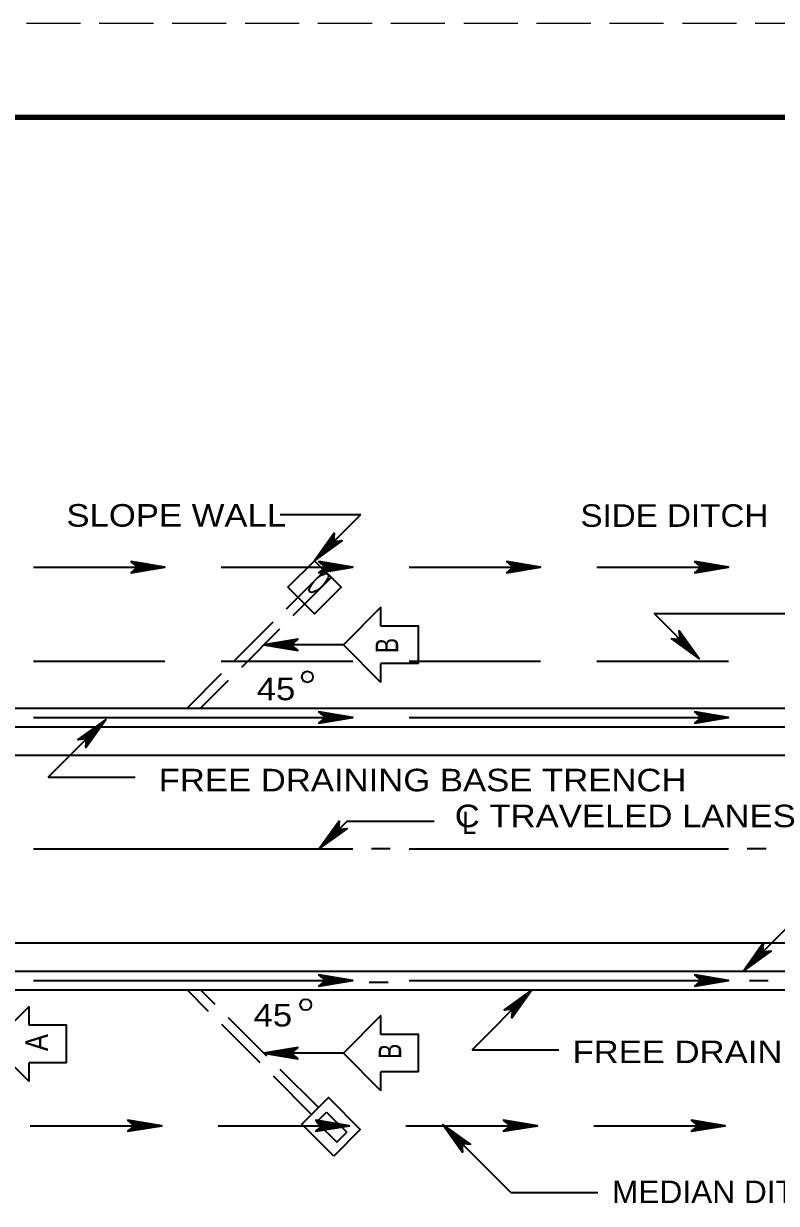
# Model space of a CAD drawing. Extents: x -48732 to -48696.6, y -117659.8 to -117637.8.
# Drawn here: x -48725.39 to -48721.38, y -117644.13 to -117637.85 of the extents above; entities that cross this region are included whole.
import ezdxf

# ---------------------------------------------------------------- set-up
doc = ezdxf.new("R2010")
doc.units = 0
doc.header["$LTSCALE"] = 0.048
doc.linetypes.add('LONG_DASHED', pattern=[7.5, 6, -1.5])
doc.layers.add('1', color=7, linetype='Continuous', lineweight=25)
doc.layers.add('3', color=7, linetype='Continuous', lineweight=35)

msp = doc.modelspace()

# ---------------------------------------------------------------- linework, layer by layer
at = {"layer": '1', "linetype": 'LONG_DASHED'}
msp.add_line((-48696.76492, -117637.84817), (-48731.96492, -117637.84817), dxfattribs=at)
at = {"layer": '1', "lineweight": 158}
msp.add_line((-48696.84825, -117638.34817), (-48729.34825, -117638.34817), dxfattribs=at)
at = {"layer": '3'}
for p, q in [((-48724.02558, -117640.46117), (-48723.59658, -117640.46117)), ((-48723.84358, -117640.70817), (-48723.59658, -117640.46117)), ((-48725.33958, -117640.74217), (-48724.63958, -117640.74217)), ((-48724.33958, -117640.74217), (-48723.63958, -117640.74217)), ((-48723.33958, -117640.74217), (-48722.63958, -117640.74217)), ((-48722.33958, -117640.74217), (-48721.63958, -117640.74217)), ((-48723.48958, -117640.95517), (-48723.68958, -117641.15517)), ((-48723.48958, -117641.05517), (-48723.48958, -117640.95517)), ((-48722.03458, -117640.98917), (-48721.33458, -117640.98917)), ((-48721.79558, -117641.22917), (-48722.03458, -117640.98917)), ((-48723.68958, -117641.15517), (-48724.11258, -117641.15517)), ((-48723.48958, -117641.35517), (-48723.68958, -117641.15517)), ((-48725.33958, -117641.24217), (-48724.63958, -117641.24217)), ((-48724.33958, -117641.24217), (-48723.63958, -117641.24217)), ((-48723.28958, -117641.25517), (-48723.48958, -117641.25517)), ((-48723.48958, -117641.35517), (-48723.48958, -117641.25517)), ((-48723.33958, -117641.24217), (-48722.63958, -117641.24217)), ((-48722.33958, -117641.24217), (-48721.63958, -117641.24217)), ((-48727.33958, -117641.49217), (-48718.76717, -117641.49217)), ((-48727.33958, -117641.59217), (-48718.76717, -117641.59217)), ((-48725.33958, -117641.54217), (-48723.63958, -117641.54217)), ((-48725.26158, -117641.86017), (-48724.95458, -117641.55317)), ((-48723.33958, -117641.54217), (-48721.63958, -117641.54217)), ((-48721.5605, -117642.89217), (-48720.2605, -117641.59217)), ((-48727.33958, -117641.74217), (-48717.32258, -117641.74217)), ((-48725.26158, -117641.86017), (-48724.79858, -117641.86017)), ((-48725.33958, -117642.24217), (-48723.63958, -117642.24217)), ((-48723.43958, -117642.24217), (-48723.53958, -117642.24217)), ((-48723.33958, -117642.24217), (-48721.63958, -117642.24217)), ((-48721.43958, -117642.24217), (-48721.53958, -117642.24217)), ((-48727.33958, -117642.74217), (-48717.32258, -117642.74217)), ((-48727.43958, -117642.89217), (-48718.76717, -117642.89217)), ((-48725.33958, -117642.94217), (-48723.63958, -117642.94217)), ((-48723.45158, -117642.95217), (-48723.55158, -117642.95217)), ((-48723.33958, -117642.94217), (-48721.63958, -117642.94217)), ((-48721.42758, -117642.94417), (-48721.52758, -117642.94417)), ((-48727.43958, -117642.99217), (-48718.76717, -117642.99217)), ((-48723.00475, -117643.311), (-48722.68592, -117642.99217)), ((-48725.36258, -117643.08017), (-48725.56258, -117643.28017)), ((-48725.36258, -117643.18017), (-48725.36258, -117643.08017)), ((-48723.48958, -117643.12917), (-48723.68958, -117643.32917)), ((-48723.48958, -117643.22917), (-48723.48958, -117643.12917)), ((-48725.36258, -117643.48017), (-48725.56258, -117643.28017)), ((-48723.68958, -117643.32917), (-48724.11258, -117643.32917)), ((-48723.48958, -117643.52917), (-48723.68958, -117643.32917)), ((-48723.00475, -117643.311), (-48722.54175, -117643.311)), ((-48725.16258, -117643.38017), (-48725.36258, -117643.38017)), ((-48725.36258, -117643.48017), (-48725.36258, -117643.38017)), ((-48723.28958, -117643.42917), (-48723.48958, -117643.42917)), ((-48723.48958, -117643.52917), (-48723.48958, -117643.42917)), ((-48723.83258, -117643.69617), (-48723.77958, -117643.64317)), ((-48723.77958, -117643.64317), (-48723.67158, -117643.75017)), ((-48725.35658, -117643.71517), (-48724.65658, -117643.71517)), ((-48724.35658, -117643.71517), (-48723.65658, -117643.71517)), ((-48723.83258, -117643.69617), (-48723.72458, -117643.80317)), ((-48723.35658, -117643.71517), (-48722.65658, -117643.71517)), ((-48722.79758, -117644.07117), (-48723.16058, -117643.70817)), ((-48722.35658, -117643.71517), (-48721.65658, -117643.71517)), ((-48723.72458, -117643.80317), (-48723.67158, -117643.75017)), ((-48722.79758, -117644.07117), (-48722.33458, -117644.07117))]:
    msp.add_line(p, q, dxfattribs=at)
at = {"layer": '3', "linetype": 'LONG_DASHED'}
for p, q in [((-48723.79058, -117640.76117), (-48724.52158, -117641.49217)), ((-48723.75458, -117640.79717), (-48724.44958, -117641.49217)), ((-48723.85858, -117643.65517), (-48724.52158, -117642.99217)), ((-48723.82258, -117643.61917), (-48724.44958, -117642.99217))]:
    msp.add_line(p, q, dxfattribs=at)
at = {"layer": '3'}
for points in [[(-48723.73758, -117640.56017), (-48723.84358, -117640.70817), (-48723.69558, -117640.60217), (-48723.70058, -117640.60217), (-48723.83058, -117640.69517), (-48723.73758, -117640.56517), (-48723.73858, -117640.57117), (-48723.81758, -117640.68217), (-48723.70658, -117640.60317), (-48723.71258, -117640.60417), (-48723.80458, -117640.66917), (-48723.73958, -117640.57717), (-48723.73958, -117640.58317), (-48723.79158, -117640.65617), (-48723.71858, -117640.60417), (-48723.72458, -117640.60517), (-48723.77958, -117640.64417), (-48723.74058, -117640.58917), (-48723.74058, -117640.59517), (-48723.76658, -117640.63117), (-48723.73058, -117640.60517), (-48723.73658, -117640.60617), (-48723.75358, -117640.61817), (-48723.74158, -117640.60117), (-48723.73758, -117640.56017), (-48723.74158, -117640.60617), (-48723.69558, -117640.60217)], [(-48724.81958, -117640.77217), (-48724.63958, -117640.74217), (-48724.81958, -117640.71217), (-48724.81458, -117640.71617), (-48724.65758, -117640.74217), (-48724.81558, -117640.76817), (-48724.81058, -117640.76417), (-48724.67658, -117640.74217), (-48724.81058, -117640.72017), (-48724.80558, -117640.72317), (-48724.69458, -117640.74217), (-48724.80558, -117640.76117), (-48724.80158, -117640.75717), (-48724.71258, -117640.74217), (-48724.80158, -117640.72717), (-48724.79658, -117640.73117), (-48724.73058, -117640.74217), (-48724.79658, -117640.75317), (-48724.79258, -117640.74917), (-48724.74958, -117640.74217), (-48724.79258, -117640.73517), (-48724.78758, -117640.73917), (-48724.76758, -117640.74217), (-48724.78758, -117640.74517), (-48724.81958, -117640.77217), (-48724.78358, -117640.74217), (-48724.81958, -117640.71217)], [(-48723.81958, -117640.77217), (-48723.63958, -117640.74217), (-48723.81958, -117640.71217), (-48723.81458, -117640.71617), (-48723.65758, -117640.74217), (-48723.81558, -117640.76817), (-48723.81058, -117640.76417), (-48723.67658, -117640.74217), (-48723.81058, -117640.72017), (-48723.80558, -117640.72317), (-48723.69458, -117640.74217), (-48723.80558, -117640.76117), (-48723.80158, -117640.75717), (-48723.71258, -117640.74217), (-48723.80158, -117640.72717), (-48723.79658, -117640.73117), (-48723.73058, -117640.74217), (-48723.79658, -117640.75317), (-48723.79258, -117640.74917), (-48723.74958, -117640.74217), (-48723.79258, -117640.73517), (-48723.78758, -117640.73917), (-48723.76758, -117640.74217), (-48723.78758, -117640.74517), (-48723.81958, -117640.77217), (-48723.78358, -117640.74217), (-48723.81958, -117640.71217)], [(-48722.81958, -117640.77217), (-48722.63958, -117640.74217), (-48722.81958, -117640.71217), (-48722.81458, -117640.71617), (-48722.65758, -117640.74217), (-48722.81558, -117640.76817), (-48722.81058, -117640.76417), (-48722.67658, -117640.74217), (-48722.81058, -117640.72017), (-48722.80558, -117640.72317), (-48722.69458, -117640.74217), (-48722.80558, -117640.76117), (-48722.80158, -117640.75717), (-48722.71258, -117640.74217), (-48722.80158, -117640.72717), (-48722.79658, -117640.73117), (-48722.73058, -117640.74217), (-48722.79658, -117640.75317), (-48722.79258, -117640.74917), (-48722.74958, -117640.74217), (-48722.79258, -117640.73517), (-48722.78758, -117640.73917), (-48722.76758, -117640.74217), (-48722.78758, -117640.74517), (-48722.81958, -117640.77217), (-48722.78358, -117640.74217), (-48722.81958, -117640.71217)], [(-48721.81958, -117640.77217), (-48721.63958, -117640.74217), (-48721.81958, -117640.71217), (-48721.81458, -117640.71617), (-48721.65758, -117640.74217), (-48721.81558, -117640.76817), (-48721.81058, -117640.76417), (-48721.67658, -117640.74217), (-48721.81058, -117640.72017), (-48721.80558, -117640.72317), (-48721.69458, -117640.74217), (-48721.80558, -117640.76117), (-48721.80158, -117640.75717), (-48721.71258, -117640.74217), (-48721.80158, -117640.72717), (-48721.79658, -117640.73117), (-48721.73058, -117640.74217), (-48721.79658, -117640.75317), (-48721.79258, -117640.74917), (-48721.74958, -117640.74217), (-48721.79258, -117640.73517), (-48721.78758, -117640.73917), (-48721.76758, -117640.74217), (-48721.78758, -117640.74517), (-48721.81958, -117640.77217), (-48721.78358, -117640.74217), (-48721.81958, -117640.71217)], [(-48723.28958, -117641.25517), (-48723.28958, -117641.05517), (-48723.48958, -117641.05517)], [(-48721.94358, -117641.12317), (-48721.79558, -117641.22917), (-48721.90158, -117641.08117), (-48721.90158, -117641.08617), (-48721.80858, -117641.21617), (-48721.93858, -117641.12317), (-48721.93258, -117641.12417), (-48721.82158, -117641.20317), (-48721.90058, -117641.09217), (-48721.89958, -117641.09817), (-48721.83458, -117641.19017), (-48721.92658, -117641.12517), (-48721.92058, -117641.12517), (-48721.84758, -117641.17717), (-48721.89958, -117641.10417), (-48721.89858, -117641.11017), (-48721.85958, -117641.16517), (-48721.91458, -117641.12617), (-48721.90858, -117641.12617), (-48721.87258, -117641.15217), (-48721.89858, -117641.11617), (-48721.89758, -117641.12217), (-48721.88558, -117641.13917), (-48721.90258, -117641.12717), (-48721.94358, -117641.12317), (-48721.89758, -117641.12717), (-48721.90158, -117641.08117)], [(-48723.93258, -117641.12517), (-48724.11258, -117641.15517), (-48723.93258, -117641.18517), (-48723.93758, -117641.18117), (-48724.09458, -117641.15517), (-48723.93658, -117641.12917), (-48723.94158, -117641.13317), (-48724.07558, -117641.15517), (-48723.94158, -117641.17717), (-48723.94658, -117641.17417), (-48724.05758, -117641.15517), (-48723.94658, -117641.13617), (-48723.95058, -117641.14017), (-48724.03958, -117641.15517), (-48723.95058, -117641.17017), (-48723.95558, -117641.16617), (-48724.02158, -117641.15517), (-48723.95558, -117641.14417), (-48723.95958, -117641.14817), (-48724.00258, -117641.15517), (-48723.95958, -117641.16217), (-48723.96458, -117641.15817), (-48723.98458, -117641.15517), (-48723.96458, -117641.15217), (-48723.93258, -117641.12517), (-48723.96858, -117641.15517), (-48723.93258, -117641.18517)], [(-48723.81958, -117641.57217), (-48723.63958, -117641.54217), (-48723.81958, -117641.51217), (-48723.81458, -117641.51617), (-48723.65758, -117641.54217), (-48723.81558, -117641.56817), (-48723.81058, -117641.56417), (-48723.67658, -117641.54217), (-48723.81058, -117641.52017), (-48723.80558, -117641.52317), (-48723.69458, -117641.54217), (-48723.80558, -117641.56117), (-48723.80158, -117641.55717), (-48723.71258, -117641.54217), (-48723.80158, -117641.52717), (-48723.79658, -117641.53117), (-48723.73058, -117641.54217), (-48723.79658, -117641.55317), (-48723.79258, -117641.54917), (-48723.74958, -117641.54217), (-48723.79258, -117641.53517), (-48723.78758, -117641.53917), (-48723.76758, -117641.54217), (-48723.78758, -117641.54517), (-48723.81958, -117641.57217), (-48723.78358, -117641.54217), (-48723.81958, -117641.51217)], [(-48721.81958, -117641.57217), (-48721.63958, -117641.54217), (-48721.81958, -117641.51217), (-48721.81458, -117641.51617), (-48721.65758, -117641.54217), (-48721.81558, -117641.56817), (-48721.81058, -117641.56417), (-48721.67658, -117641.54217), (-48721.81058, -117641.52017), (-48721.80558, -117641.52317), (-48721.69458, -117641.54217), (-48721.80558, -117641.56117), (-48721.80158, -117641.55717), (-48721.71258, -117641.54217), (-48721.80158, -117641.52717), (-48721.79658, -117641.53117), (-48721.73058, -117641.54217), (-48721.79658, -117641.55317), (-48721.79258, -117641.54917), (-48721.74958, -117641.54217), (-48721.79258, -117641.53517), (-48721.78758, -117641.53917), (-48721.76758, -117641.54217), (-48721.78758, -117641.54517), (-48721.81958, -117641.57217), (-48721.78358, -117641.54217), (-48721.81958, -117641.51217)], [(-48725.06058, -117641.70117), (-48724.95458, -117641.55317), (-48725.10258, -117641.65917), (-48725.09758, -117641.65917), (-48724.96758, -117641.56617), (-48725.06058, -117641.69617), (-48725.05958, -117641.69017), (-48724.98058, -117641.57917), (-48725.09158, -117641.65817), (-48725.08558, -117641.65717), (-48724.99358, -117641.59217), (-48725.05858, -117641.68417), (-48725.05858, -117641.67817), (-48725.00658, -117641.60517), (-48725.07958, -117641.65717), (-48725.07358, -117641.65617), (-48725.01858, -117641.61717), (-48725.05758, -117641.67217), (-48725.05758, -117641.66617), (-48725.03158, -117641.63017), (-48725.06758, -117641.65617), (-48725.06158, -117641.65517), (-48725.04458, -117641.64317), (-48725.05658, -117641.66017), (-48725.06058, -117641.70117), (-48725.05658, -117641.65517), (-48725.10258, -117641.65917)], [(-48723.81758, -117642.24117), (-48723.66958, -117642.09317), (-48723.20658, -117642.09317)], [(-48723.71158, -117642.09317), (-48723.81758, -117642.24117), (-48723.66958, -117642.13517), (-48723.67458, -117642.13517), (-48723.80458, -117642.22817), (-48723.71158, -117642.09817), (-48723.71258, -117642.10417), (-48723.79158, -117642.21517), (-48723.68058, -117642.13617), (-48723.68658, -117642.13717), (-48723.77858, -117642.20217), (-48723.71358, -117642.11017), (-48723.71358, -117642.11617), (-48723.76558, -117642.18917), (-48723.69258, -117642.13717), (-48723.69858, -117642.13817), (-48723.75358, -117642.17717), (-48723.71458, -117642.12217), (-48723.71458, -117642.12817), (-48723.74058, -117642.16417), (-48723.70458, -117642.13817), (-48723.71058, -117642.13917), (-48723.72758, -117642.15117), (-48723.71558, -117642.13417), (-48723.71158, -117642.09317), (-48723.71558, -117642.13917), (-48723.66958, -117642.13517)], [(-48721.4545, -117642.74417), (-48721.5605, -117642.89217), (-48721.4125, -117642.78617), (-48721.4175, -117642.78617), (-48721.5475, -117642.87917), (-48721.4545, -117642.74917), (-48721.4555, -117642.75517), (-48721.5345, -117642.86617), (-48721.4235, -117642.78717), (-48721.4295, -117642.78817), (-48721.5215, -117642.85317), (-48721.4565, -117642.76117), (-48721.4565, -117642.76717), (-48721.5085, -117642.84017), (-48721.4355, -117642.78817), (-48721.4415, -117642.78917), (-48721.4965, -117642.82817), (-48721.4575, -117642.77317), (-48721.4575, -117642.77917), (-48721.4835, -117642.81517), (-48721.4475, -117642.78917), (-48721.4535, -117642.79017), (-48721.4705, -117642.80217), (-48721.4585, -117642.78517), (-48721.4545, -117642.74417), (-48721.4585, -117642.79017), (-48721.4125, -117642.78617)], [(-48723.81958, -117642.97217), (-48723.63958, -117642.94217), (-48723.81958, -117642.91217), (-48723.81458, -117642.91617), (-48723.65758, -117642.94217), (-48723.81558, -117642.96817), (-48723.81058, -117642.96417), (-48723.67658, -117642.94217), (-48723.81058, -117642.92017), (-48723.80558, -117642.92317), (-48723.69458, -117642.94217), (-48723.80558, -117642.96117), (-48723.80158, -117642.95717), (-48723.71258, -117642.94217), (-48723.80158, -117642.92717), (-48723.79658, -117642.93117), (-48723.73058, -117642.94217), (-48723.79658, -117642.95317), (-48723.79258, -117642.94917), (-48723.74958, -117642.94217), (-48723.79258, -117642.93517), (-48723.78758, -117642.93917), (-48723.76758, -117642.94217), (-48723.78758, -117642.94517), (-48723.81958, -117642.97217), (-48723.78358, -117642.94217), (-48723.81958, -117642.91217)], [(-48721.81958, -117642.97217), (-48721.63958, -117642.94217), (-48721.81958, -117642.91217), (-48721.81458, -117642.91617), (-48721.65758, -117642.94217), (-48721.81558, -117642.96817), (-48721.81058, -117642.96417), (-48721.67658, -117642.94217), (-48721.81058, -117642.92017), (-48721.80558, -117642.92317), (-48721.69458, -117642.94217), (-48721.80558, -117642.96117), (-48721.80158, -117642.95717), (-48721.71258, -117642.94217), (-48721.80158, -117642.92717), (-48721.79658, -117642.93117), (-48721.73058, -117642.94217), (-48721.79658, -117642.95317), (-48721.79258, -117642.94917), (-48721.74958, -117642.94217), (-48721.79258, -117642.93517), (-48721.78758, -117642.93917), (-48721.76758, -117642.94217), (-48721.78758, -117642.94517), (-48721.81958, -117642.97217), (-48721.78358, -117642.94217), (-48721.81958, -117642.91217)], [(-48722.79192, -117643.14017), (-48722.68592, -117642.99217), (-48722.83392, -117643.09817), (-48722.82892, -117643.09817), (-48722.69892, -117643.00517), (-48722.79192, -117643.13517), (-48722.79092, -117643.12917), (-48722.71192, -117643.01817), (-48722.82292, -117643.09717), (-48722.81692, -117643.09617), (-48722.72492, -117643.03117), (-48722.78992, -117643.12317), (-48722.78992, -117643.11717), (-48722.73792, -117643.04417), (-48722.81092, -117643.09617), (-48722.80492, -117643.09517), (-48722.74992, -117643.05617), (-48722.78892, -117643.11117), (-48722.78892, -117643.10517), (-48722.76292, -117643.06917), (-48722.79892, -117643.09517), (-48722.79292, -117643.09417), (-48722.77592, -117643.08217), (-48722.78792, -117643.09917), (-48722.79192, -117643.14017), (-48722.78792, -117643.09417), (-48722.83392, -117643.09817)], [(-48725.16258, -117643.38017), (-48725.16258, -117643.18017), (-48725.36258, -117643.18017)], [(-48723.28958, -117643.42917), (-48723.28958, -117643.22917), (-48723.48958, -117643.22917)], [(-48723.93258, -117643.29917), (-48724.11258, -117643.32917), (-48723.93258, -117643.35917), (-48723.93758, -117643.35517), (-48724.09458, -117643.32917), (-48723.93658, -117643.30317), (-48723.94158, -117643.30717), (-48724.07558, -117643.32917), (-48723.94158, -117643.35117), (-48723.94658, -117643.34817), (-48724.05758, -117643.32917), (-48723.94658, -117643.31017), (-48723.95058, -117643.31417), (-48724.03958, -117643.32917), (-48723.95058, -117643.34417), (-48723.95558, -117643.34017), (-48724.02158, -117643.32917), (-48723.95558, -117643.31817), (-48723.95958, -117643.32217), (-48724.00258, -117643.32917), (-48723.95958, -117643.33617), (-48723.96458, -117643.33217), (-48723.98458, -117643.32917), (-48723.96458, -117643.32617), (-48723.93258, -117643.29917), (-48723.96858, -117643.32917), (-48723.93258, -117643.35917)], [(-48724.83658, -117643.74517), (-48724.65658, -117643.71517), (-48724.83658, -117643.68517), (-48724.83158, -117643.68917), (-48724.67458, -117643.71517), (-48724.83258, -117643.74117), (-48724.82758, -117643.73717), (-48724.69358, -117643.71517), (-48724.82758, -117643.69317), (-48724.82258, -117643.69617), (-48724.71158, -117643.71517), (-48724.82258, -117643.73417), (-48724.81858, -117643.73017), (-48724.72958, -117643.71517), (-48724.81858, -117643.70017), (-48724.81358, -117643.70417), (-48724.74758, -117643.71517), (-48724.81358, -117643.72617), (-48724.80958, -117643.72217), (-48724.76658, -117643.71517), (-48724.80958, -117643.70817), (-48724.80458, -117643.71217), (-48724.78458, -117643.71517), (-48724.80458, -117643.71817), (-48724.83658, -117643.74517), (-48724.80058, -117643.71517), (-48724.83658, -117643.68517)], [(-48723.83658, -117643.74517), (-48723.65658, -117643.71517), (-48723.83658, -117643.68517), (-48723.83158, -117643.68917), (-48723.67458, -117643.71517), (-48723.83258, -117643.74117), (-48723.82758, -117643.73717), (-48723.69358, -117643.71517), (-48723.82758, -117643.69317), (-48723.82258, -117643.69617), (-48723.71158, -117643.71517), (-48723.82258, -117643.73417), (-48723.81858, -117643.73017), (-48723.72958, -117643.71517), (-48723.81858, -117643.70017), (-48723.81358, -117643.70417), (-48723.74758, -117643.71517), (-48723.81358, -117643.72617), (-48723.80958, -117643.72217), (-48723.76658, -117643.71517), (-48723.80958, -117643.70817), (-48723.80458, -117643.71217), (-48723.78458, -117643.71517), (-48723.80458, -117643.71817), (-48723.83658, -117643.74517), (-48723.80058, -117643.71517), (-48723.83658, -117643.68517)], [(-48723.01258, -117643.81417), (-48723.16058, -117643.70817), (-48723.05458, -117643.85617), (-48723.05458, -117643.85117), (-48723.14758, -117643.72117), (-48723.01758, -117643.81417), (-48723.02358, -117643.81317), (-48723.13458, -117643.73417), (-48723.05558, -117643.84517), (-48723.05658, -117643.83917), (-48723.12158, -117643.74717), (-48723.02958, -117643.81217), (-48723.03558, -117643.81217), (-48723.10858, -117643.76017), (-48723.05658, -117643.83317), (-48723.05758, -117643.82717), (-48723.09658, -117643.77217), (-48723.04158, -117643.81117), (-48723.04758, -117643.81117), (-48723.08358, -117643.78517), (-48723.05758, -117643.82117), (-48723.05858, -117643.81517), (-48723.07058, -117643.79817), (-48723.05358, -117643.81017), (-48723.01258, -117643.81417), (-48723.05858, -117643.81017), (-48723.05458, -117643.85617)], [(-48722.83658, -117643.74517), (-48722.65658, -117643.71517), (-48722.83658, -117643.68517), (-48722.83158, -117643.68917), (-48722.67458, -117643.71517), (-48722.83258, -117643.74117), (-48722.82758, -117643.73717), (-48722.69358, -117643.71517), (-48722.82758, -117643.69317), (-48722.82258, -117643.69617), (-48722.71158, -117643.71517), (-48722.82258, -117643.73417), (-48722.81858, -117643.73017), (-48722.72958, -117643.71517), (-48722.81858, -117643.70017), (-48722.81358, -117643.70417), (-48722.74758, -117643.71517), (-48722.81358, -117643.72617), (-48722.80958, -117643.72217), (-48722.76658, -117643.71517), (-48722.80958, -117643.70817), (-48722.80458, -117643.71217), (-48722.78458, -117643.71517), (-48722.80458, -117643.71817), (-48722.83658, -117643.74517), (-48722.80058, -117643.71517), (-48722.83658, -117643.68517)], [(-48721.83658, -117643.74517), (-48721.65658, -117643.71517), (-48721.83658, -117643.68517), (-48721.83158, -117643.68917), (-48721.67458, -117643.71517), (-48721.83258, -117643.74117), (-48721.82758, -117643.73717), (-48721.69358, -117643.71517), (-48721.82758, -117643.69317), (-48721.82258, -117643.69617), (-48721.71158, -117643.71517), (-48721.82258, -117643.73417), (-48721.81858, -117643.73017), (-48721.72958, -117643.71517), (-48721.81858, -117643.70017), (-48721.81358, -117643.70417), (-48721.74758, -117643.71517), (-48721.81358, -117643.72617), (-48721.80958, -117643.72217), (-48721.76658, -117643.71517), (-48721.80958, -117643.70817), (-48721.80458, -117643.71217), (-48721.78458, -117643.71517), (-48721.80458, -117643.71817), (-48721.83658, -117643.74517), (-48721.80058, -117643.71517), (-48721.83658, -117643.68517)]]:
    msp.add_lwpolyline(points, dxfattribs=at)
for points in [[(-48723.98458, -117640.84917), (-48723.84358, -117640.70817), (-48723.70158, -117640.84917), (-48723.84358, -117640.99117)], [(-48723.73958, -117643.87717), (-48723.91058, -117643.70617), (-48723.76858, -117643.56517), (-48723.59958, -117643.73617)]]:
    msp.add_lwpolyline(points, close=True, dxfattribs=at)
for centre in [(-48723.88058, -117641.32567), (-48723.88958, -117643.07067)]:
    msp.add_circle(centre, 0.02935, dxfattribs=at)
msp.add_ellipse((-48723.82008, -117640.82617), major_axis=(-0.0485, -0.047), ratio=0.364314, dxfattribs=at)

# ---------------------------------------------------------------- texts
for s, width, p in [('SLOPE WALL', 1.15, (-48725.16358, -117640.52617)), ('SIDE DITCH', 1.1, (-48722.42758, -117640.52717)), ('45', 1.15, (-48724.15058, -117641.45017)), ('FREE DRAINING BASE TRENCH', 1.15, (-48724.67258, -117641.93517)), ('C TRAVELED LANES', 1.15, (-48723.09658, -117642.12617)), ('L', 0.85, (-48723.05758, -117642.16317)), ('45', 1.15, (-48724.16758, -117643.18717)), ('FREE DRAINING BASE TRENCH', 1.15, (-48722.46992, -117643.38225)), ('MEDIAN DITCH', 1.05, (-48722.25958, -117644.12717))]:
    msp.add_text(s, height=0.12, dxfattribs=dict(at, width=width)).set_placement(p)
for s, width, p in [('B', 0.75, (-48723.39758, -117641.19917)), ('A', 0.85, (-48725.26158, -117643.31817)), ('B', 0.75, (-48723.38158, -117643.35917))]:
    msp.add_text(s, height=0.12, rotation=90, dxfattribs=dict(at, width=width)).set_placement(p)

doc.saveas('drawing.dxf')
